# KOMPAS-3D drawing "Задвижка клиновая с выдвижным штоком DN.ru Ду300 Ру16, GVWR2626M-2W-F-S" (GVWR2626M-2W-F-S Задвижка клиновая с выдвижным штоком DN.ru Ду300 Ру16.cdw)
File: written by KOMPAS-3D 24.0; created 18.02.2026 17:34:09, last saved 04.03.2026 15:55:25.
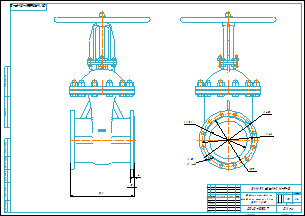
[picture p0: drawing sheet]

Document properties: Автор: R2D2; Форматы листов документа: A2; Полное имя файла: GVWR2626M-2W-F-S Задвижка клиновая с выдвижным штоком DN.ru Ду300 Ру16.m3d; Масса: 215; Наименование: Задвижка клиновая с выдвижным штоком DN.ru Ду300 Ру16; Количество листов документа: 1; Примечание: D040-10507

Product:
- Part/product: Задвижка клиновая с выдвижным штоком DN.ru Ду300 Ру16  | designation GVWR2626M-2W-F-S
    Масса: 215
    Раздел спецификации: Прочие изделия
    Примечание: D040-10507

Referenced files in E:\Работа\Зайцев\Для компаса\: чертеж DN.ru А3.cdt
Referenced files in E:\Работа\Зайцев\GVWR2626M-2W-F-S Задвижка клиновая с выдвижным штоком DN.ru Ду50-300 Ру16\DN300\: GVWR2626M-2W-F-S Задвижка клиновая с выдвижным штоком DN.ru Ду300 Ру16.m3d
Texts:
  чертеж DN.ru А3.cdt
  Задвижка клиновая с
  выдвижным штоком DN.ru
  Ду300 Ру16
  GVWR2626M-2W-F-S
  Задвижка клиновая с выдвижным штоком DN.ru Ду300 Ру16
  GVWR2626M-2W-F-S Задвижка клиновая с выдвижным штоком DN.ru Ду300 Ру16
Dimensions and other numbers on the sheet: 1:4; 0; 1; 2; 215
